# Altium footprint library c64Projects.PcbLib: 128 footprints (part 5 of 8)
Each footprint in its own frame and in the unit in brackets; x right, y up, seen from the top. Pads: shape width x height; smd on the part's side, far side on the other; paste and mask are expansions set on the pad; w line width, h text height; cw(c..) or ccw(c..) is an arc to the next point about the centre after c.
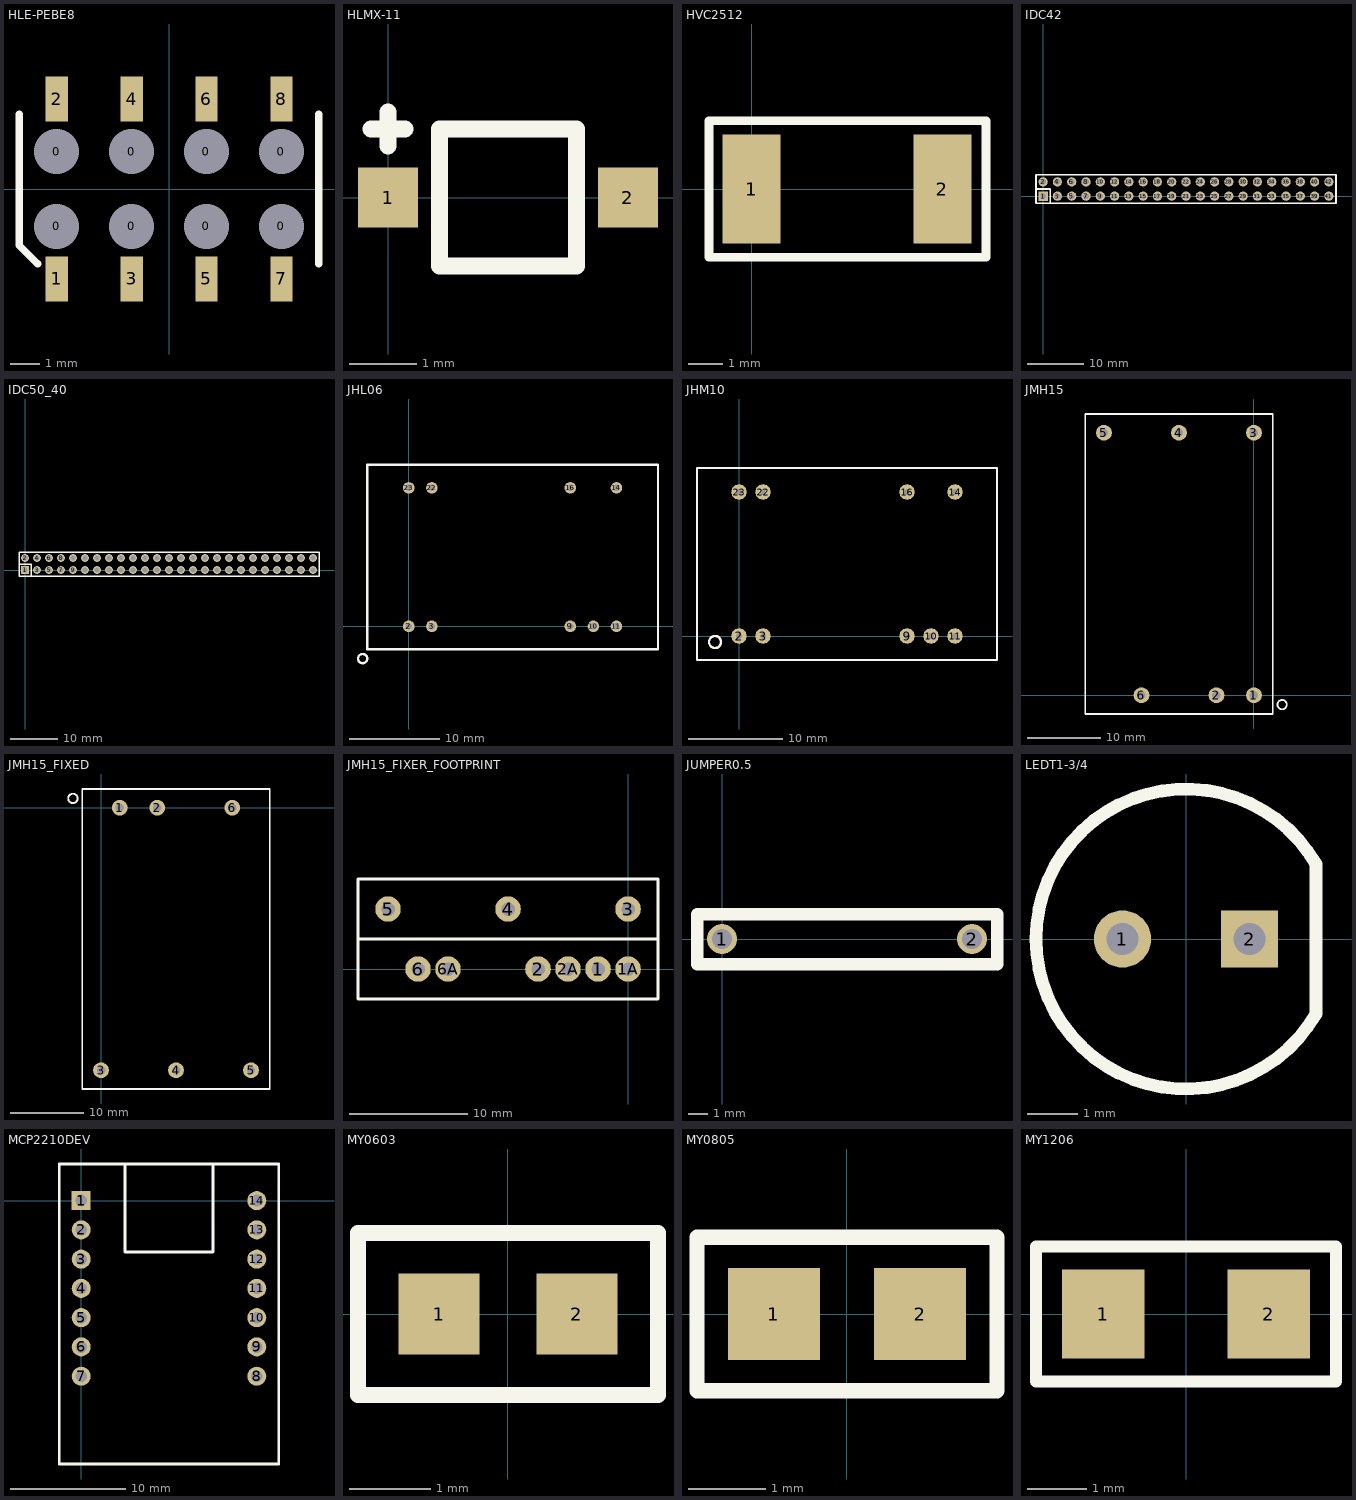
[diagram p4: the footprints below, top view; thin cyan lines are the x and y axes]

## HLE-PEBE8 [mil]
pads (16):
  round 20 hole 60 unplated: 0(-150,-50) 0(-150,50) 0(-50,-50) 0(-50,50) 0(50,-50) 0(50,50) 0(150,-50) 0(150,50)
  rect 30x60 smd: 1(-150,-120) 2(-150,120) 3(-50,-120) 4(-50,120) 5(50,-120) 6(50,120) 7(150,-120) 8(150,120)
Top Overlay:
  lines w10: -200,100 -200,-75 -175,-100 ; 200,-100 200,100

## HLMX-11 [mil]
pads (2):
  rect 35x35 smd: 1(0,0) 2(140,0)
Top Overlay:
  lines w10: -10,40 10,40 ; 0,30 0,50 ; 30,-40 30,40 110,40 110,-40 30,-40

## HVC2512 [mm]
pads (2):
  rect 1.7x3.2 smd: 1(0,0) 2(5.6,0)
Top Overlay:
  lines w0.254: -1.25,-2 6.875,-2 6.875,2 -1.25,2 -1.25,-2

## IDC42 [mil]
pads (42):
  rect 65x65 hole 40: 1(0,0)
  round 65 hole 40: 2(0,100) 3(100,0) 4(100,100) 5(200,0) 6(200,100) 7(300,0) 8(300,100) 9(400,0) 10(400,100) 11(500,0) 12(500,100) 13(600,0) 14(600,100) 15(700,0) 16(700,100) 17(800,0) 18(800,100) 19(900,0) 20(900,100) 21(1000,0) 22(1000,100) 23(1100,0) 24(1100,100) 25(1200,0) 26(1200,100) 27(1300,0) 28(1300,100) 29(1400,0) 30(1400,100) 31(1500,0) 32(1500,100) 33(1600,0) 34(1600,100) 35(1700,0) 36(1700,100) 37(1800,0) 38(1800,100) 39(1900,0) 40(1900,100) 41(2000,0) 42(2000,100)
Top Overlay:
  lines w12: -50,50 50,50 50,-50 ; -50,-50 2050,-50 2050,150 -50,150 -50,-50

## IDC50_40 [mil]
pads (50):
  rect 65x65 hole 40: 1(0,0)
  round 65 hole 40: 2(0,100) 3(100,0) 4(100,100) 5(200,0) 6(200,100) 7(300,0) 8(300,100) 9(400,0) 10(400,100) 11(500,0) 12(500,100) 13(600,0) 14(600,100) 15(700,0) 16(700,100) 17(800,0) 18(800,100) 19(900,0) 20(900,100) 21(1000,0) 22(1000,100) 23(1100,0) 24(1100,100) 25(1200,0) 26(1200,100) 27(1300,0) 28(1300,100) 29(1400,0) 30(1400,100) 31(1500,0) 32(1500,100) 33(1600,0) 34(1600,100) 35(1700,0) 36(1700,100) 37(1800,0) 38(1800,100) 39(1900,0) 40(1900,100) 41(2000,0) 42(2000,100) 43(2100,0) 44(2100,100) 45(2200,0) 46(2200,100) 47(2300,0) 48(2300,100) 49(2400,0) 50(2400,100)
Top Overlay:
  lines w12: -50,50 50,50 50,-50 ; -50,-50 -50,150 2450,150 2450,-50 -50,-50

## JHL06 [mil]
pads (9):
  round 50 hole 28: 2(0,0) 3(100,0) 9(700,0) 10(800,0) 11(900,0) 14(900,600) 16(700,600) 22(100,600) 23(0,600)
Top Overlay:
  circle w10: c-200,-140 r20
  lines w10: -180,-100 -180,700 1080,700 1080,-100 -180,-100

## JHM10 [mil]
pads (9):
  round 65 hole 25: 2(0,0) 3(100,0) 9(700,0) 10(800,0) 11(900,0) 14(900,600) 16(700,600) 22(100,600) 23(0,600)
Top Overlay:
  circle w10: c-100,-25 r25
  lines w10: -175,-100 1075,-100 1075,700 -175,700 -175,-100

## JMH15 [mil]
pads (6):
  round 85 hole 45: 1(0,0) 2(-200,0) 3(0,1400) 4(-400,1400) 5(-800,1400) 6(-600,0)
Top Overlay:
  circle w10: c150,-50 r25
  lines w10: -900,-100 -900,1500 100,1500 100,-100 -900,-100

## JMH15_FIXED [mil]
pads (6):
  round 85 hole 45: 1(100,0) 2(300,0) 3(0,-1400) 4(400,-1400) 5(800,-1400) 6(700,0)
Top Overlay:
  circle w10: c-150,50 r25
  lines w10: -100,-1500 900,-1500 900,100 -100,100 -100,-1500

## JMH15_FIXER_FOOTPRINT [mil]
pads (9):
  round 85 hole 45: 1(-100,0) 1A(0,0) 2(-300,0) 2A(-200,0) 3(0,200) 4(-400,200) 5(-800,200) 6(-700,0) 6A(-600,0)
Top Overlay:
  lines w10: -900,100 100,100 ; -900,-100 100,-100 100,300 -900,300 -900,-100

## JUMPER0.5 [mil]
pads (2):
  round 60 hole 40: 1(0,0) 2(500,0)
Top Overlay:
  lines w25: -50,-50 -50,50 550,50 550,-50 -50,-50

## LEDT1-3/4 [mil]
pads (2):
  round 45 hole 25: 1(-50,0)
  rect 45x45 hole 25: 2(50,0)
Top Overlay:
  lines w10: 102.29,-59.06 cw(c0,0) 102.29,59.06 102.29,-59.06

## MCP2210DEV [mil]
pads (14):
  rect 65x65 hole 40: 1(0,0)
  round 65 hole 40: 2(0,-100) 3(0,-200) 4(0,-300) 5(0,-400) 6(0,-500) 7(0,-600) 8(600,-600) 9(600,-500) 10(600,-400) 11(600,-300) 12(600,-200) 13(600,-100) 14(600,0)
Top Overlay:
  lines w10: 150,125 150,-175 450,-175 450,125 ; -75,-900 675,-900 675,125 -75,125 -75,-900

## MY0603 [mm]
pads (2):
  rect 1x1 smd: 1(-0.85,0) 2(0.85,0)
Top Overlay:
  lines w0.2: -1.85,-1 -1.85,0 -1.85,1 1.85,1 1.85,-1 -1.85,-1

## MY0805 [mm]
pads (2):
  rect 1.2x1.2 smd: 1(-0.95,0) 2(0.95,0)
Top Overlay:
  lines w0.2: -1.95,-1 1.95,-1 1.95,1 -1.95,1 -1.95,0 -1.95,-1

## MY1206 [mm]
pads (2):
  rect 1.4x1.5 smd: 1(-1.4,0) 2(1.4,0)
Top Overlay:
  lines w0.2: -2.54,-1.143 -2.54,0.19 -2.54,1.143 2.54,1.143 2.54,-1.143 -2.54,-1.143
